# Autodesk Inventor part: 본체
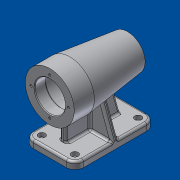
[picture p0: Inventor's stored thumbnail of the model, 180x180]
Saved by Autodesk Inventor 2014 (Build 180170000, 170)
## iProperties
Created: 2018-09
Part Number: 본체
Material: 알루미늄 6061
Document SubType Name: Modeling
Designer: 702-20
Density: 2.71 g/cm^3
Appearance: 알루미늄 - 평지
Mass: 736.704 g
Surface Area: 677.019 cm^2
Volume: 271.846 cm^3
Author: 702-20
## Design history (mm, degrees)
sketch "스케치5"
  geometry: C1 r 34 at (0, 0); 1 further point
  constraints: 1 centre point, 1 coincident
  dimensions: "d16" = 68 diameter of C1
extrude "돌출1" new body sketch "스케치5" distance "d17" = 28; taper "d18" = 0 deg
sketch "스케치6"
  geometry: C1 r 34 at (0, 0) reference
extrude "돌출2" join sketch "스케치6" distance "d19" = 92; taper "d20" = -7 deg
sketch "스케치7"
  geometry: L1 (0, 34)-(28, 34) reference; L2 (0, 34)-(0, -34) reference; L3 (0, -34)-(28, -34) reference; L4 (0, 34)-(117.083, 34); L5 (0, -34)-(117.083, -34); L6 (0, 0)-(112, 0); A1 r 80 centre (32, 0) between (104.415, -34) and (104.415, 34)
  constraints: 6 end point, 4 parallel, 3 point on circle, 2 point on line, 1 centre point
  dimensions: "d21" = 112 distance of L6.end L6.start; "d22" = 80 radius of A1
node "작업 평면2"
sketch "스케치8"
  geometry: L1 (-34, 0)-(-34, 28) reference; L2 (34, 0)-(34, 28) reference; L3 (-34, 0)-(34, 0) reference; L4 (-34, 0)-(-34, 112.065); L5 (34, 0)-(34, 112.065); A1 r 80 centre (-0.332, 24.439) between (45.834, 89.774) and (-45.954, 90.155); 3 further points
  constraints: 4 end point, 3 point on circle, 2 parallel, 1 centre point, 1 coincident, 1 perpendicular, 1 other
  dimensions: "d23" = 80 radius of A1
feature "스윕 곡면2" sketch "스케치8" dims "d24" = 0
feature "분할2"
sketch "스케치9"
  geometry: L1 (0, 0)-(0, 118.713); L2 (0, 106)-(7.5, 106); L3 (10.5, 103)-(10.5, 103); L4 (10.5, 103)-(15.7, 103); L5 (16, 102.7)-(16, 99); L6 (16, 99)-(17.2, 99); L7 (17.5, 98.7)-(17.5, 81); L8 (17.5, 81)-(20.7, 81); L9 (21, 80.7)-(21, 69); L10 (21, 69)-(21, 69); L11 (24, 66)-(24, 18); L12 (21, 15)-(21, 15); L13 (21, 15)-(21, 0); L14 (21, 0)-(0, 0); A1 r 3 centre (7.5, 103) between (10.5, 103) and (7.5, 106); A2 r 3 centre (21, 66) between (24, 66) and (21, 69); A3 r 3 centre (21, 18) between (21, 15) and (24, 18); A4 r 0.3 centre (15.7, 102.7) between (16, 102.7) and (15.7, 103); A5 r 0.3 centre (17.2, 98.7) between (17.5, 98.7) and (17.2, 99); A6 r 0.3 centre (20.7, 80.7) between (21, 80.7) and (20.7, 81); 3 further points
  constraints: 28 end point, 12 point on circle, 12 tangent, 9 parallel, 7 point on line, 6 centre point, 4 equal radius, 4 perpendicular, 1 vertical
  dimensions: "d25" = 15 distance between parallel lines of L14 L12; "d26" = 54 distance between parallel lines of L10 L12; "d27" = 12 distance between parallel lines of L8 L10; "d28" = 18 distance from line of L5.end L8; "d29" = 4 vertical distance of point (16, 103) point (17.5, 99); "d30" = 3 distance between parallel lines of L2 L4; "d31" = 42 diameter of L13 L1; "d32" = 48 diameter of L11 L1; "d33" = 42 diameter of L9 L1; "d34" = 35 diameter of L7 L1; "d35" = 32 diameter of L5 L1; "d36" = 21 diameter of point (10.5, 106) L1; "d37" = 3 radius of A1; "d38" = 0.3 radius of A4
revolve "회전2" sketch "스케치9" stored, may be unused: angle "d39" = 90 deg
node "작업 평면3"
sketch "스케치10"
  geometry: L1 (-23, 112)-(23, 112); L2 (35, 100)-(35, 12); L3 (23, 0)-(-23, 0); L4 (-35, 12)-(-35, 100); A1 r 12 centre (-23, 100) between (-23, 112) and (-35, 100); A2 r 12 centre (23, 100) between (35, 100) and (23, 112); A3 r 12 centre (23, 12) between (23, 0) and (35, 12); A4 r 12 centre (-23, 12) between (-35, 12) and (-23, 0); 5 further points
  constraints: 8 end point, 8 point on circle, 8 tangent, 6 point on line, 4 centre point, 3 equal radius, 2 parallel, 1 coincident, 1 horizontal, 1 midpoint, 1 perpendicular
  dimensions: "d41" = 70 distance of point (35, 0) point (-35, 0); "d42" = 112 distance of point (35, 112) point (35, 0); "d43" = 12 radius of A1
extrude "돌출3" join sketch "스케치10" distance "d44" = 10; taper "d45" = 0 deg
sketch "스케치11"
  geometry: L1 (18, -31.243)-(18, -64); L2 (83.432, -24.56)-(94, -64); L3 (108.27, -24.144)-(28, -34) reference; L4 (28, -34)-(0, -34) reference; L5 (0, -34)-(0, -21) reference; L6 (0, -21)-(15, -21) reference; L7 (18, -24)-(66, -24) reference; L8 (69, -21)-(80.7, -21) reference; L9 (81, -20.7)-(81, -17.5) reference; L10 (81, -17.5)-(98.7, -17.5) reference; L11 (99, -17.2)-(99, -16) reference; L12 (99, -16)-(102.7, -16) reference; L13 (103, -15.7)-(103, -10.5) reference; L14 (106, -7.5)-(106, 7.5) reference; L15 (103, 10.5)-(103, 15.7) reference; L16 (102.7, 16)-(99, 16) reference; L17 (99, 16)-(99, 17.2) reference; L18 (98.7, 17.5)-(81, 17.5) reference; L19 (81, 17.5)-(81, 20.7) reference; L20 (80.7, 21)-(69, 21) reference; L21 (66, 24)-(18, 24) reference; L22 (15, 21)-(0, 21) reference; L23 (0, 21)-(0, 34) reference; L24 (0, 34)-(28, 34) reference; L25 (28, 34)-(108.27, 24.144) reference; L26 (0, -74)-(0, -64) reference; L27 (0, -64)-(112, -64) reference; L28 (112, -64)-(112, -74) reference; L29 (112, -74)-(0, -74) reference; L30 (18, -31.243)-(34.345, -31.243); L31 (34.345, -31.243)-(83.432, -24.56); A1 r 3 centre (18, -21) between (15, -21) and (18, -24) reference; A2 r 3 centre (66, -21) between (66, -24) and (69, -21) reference; A3 r 0.3 centre (80.7, -20.7) between (80.7, -21) and (81, -20.7) reference; A4 r 0.3 centre (98.7, -17.2) between (98.7, -17.5) and (99, -17.2) reference; A5 r 0.3 centre (102.7, -15.7) between (102.7, -16) and (103, -15.7) reference; A6 r 3 centre (103, -7.5) between (103, -10.5) and (106, -7.5) reference; A7 r 3 centre (103, 7.5) between (106, 7.5) and (103, 10.5) reference; A8 r 0.3 centre (102.7, 15.7) between (103, 15.7) and (102.7, 16) reference; A9 r 0.3 centre (98.7, 17.2) between (99, 17.2) and (98.7, 17.5) reference; A10 r 0.3 centre (80.7, 20.7) between (81, 20.7) and (80.7, 21) reference; A11 r 3 centre (66, 21) between (69, 21) and (66, 24) reference; A12 r 3 centre (18, 21) between (18, 24) and (15, 21) reference; 3 further points
  constraints: 8 end point, 6 point on line, 1 parallel, 1 vertical, 1 vertical alignment
  dimensions: "d46" = 18 distance from line of L2.end L28; "d47" = 18 distance between parallel lines of L1 L26; "d48" = 105 deg angle of L2 L27
extrude "돌출4" join sketch "스케치11" stored distance "d49" = 8; taper "d50" = 0 deg
node "작업 평면4"
sketch "스케치12"
  geometry: L1 (35, -64)-(35, -74) reference; L2 (35, -74)-(-35, -74) reference; L3 (-35, -74)-(-35, -64) reference; L4 (-35, -64)-(-4, -64) reference; L5 (-4, -64)-(-4, -30.562) reference; L6 (-4, -30.562)-(0, -30.562) reference; L7 (0, -30.562)-(4, -30.562) reference; L8 (4, -30.562)-(4, -64) reference; L9 (4, -64)-(35, -64) reference; L10 (-35, -64)-(-20.089, -23.032); C1 r 24 at (0, 0) reference; A1 r 30.562 centre (0, 0) between (0, -30.562) and (-20.089, -23.032) reference; 1 further point
  constraints: 2 end point, 1 point on circle
  dimensions: "d53" = 20 deg angle of L10 L3
feature "리브1" sketch "스케치12" dims "d54" = 1, "d55" = 8, "d56" = 0, "d57" = 0, "d58" = 1, "d59" = 1
fillet "모깎기1" dims "d60" = 3
fillet "모깎기2" dims "d61" = 3
fillet "모깎기3" dims "d62" = 3
fillet "모깎기4" dims "d63" = 3
fillet "모깎기5" dims "d64" = 3
fillet "모깎기6" dims "d65" = 3
hole "구멍1" diameter "d68" = 5.5; stored, may be unused: countersink angle "d72" = 90 deg, drill point angle "d74" = 118 deg; dims "d66" = 10, "d67" = 10, "d69" = 6, "d70" = 9.5, "d71" = 5.4, "d73" = 8
node "작업 평면5"
node "작업 평면6"
sketch "스케치13"
  geometry: C1 r 21 at (0, 0) reference; 1 further point
  dimensions: "d75" = 26 distance of C1.centre point (0, 26)
hole "구멍2" sketch "스케치13" at (0, 26) diameter "d76" = 3.242; stored, may be unused: countersink angle "d80" = 90 deg, drill point angle "d82" = 118 deg; dims "d77" = 8, "d78" = 9.5, "d79" = 5.4, "d81" = 11
chamfer "모따기1" distance "d86" = 1; stored, may be unused: second distance "d87" = 2, angle "d88" = 45 deg
sketch "스케치14"
  geometry: L1 (0, 88)-(0, 0) reference; L2 (7, 39.391)-(7, 0) reference; L3 (3, 110.486)-(3, -60.871); L4 (0, 44)-(17.321, 44); 2 further points
  constraints: 4 end point, 1 midpoint, 1 parallel, 1 perpendicular, 1 other
  dimensions: "d89" = 3 distance between parallel lines of L3 L1
feature "엠보싱1" sketch "스케치14" dims "d90" = 0.5, "d91" = 0
node "솔리드2"
mirror "대칭1"
mirror "대칭2"
mirror "대칭3"
pattern_circular "원형 패턴1" dims angle "d84" = 360 deg
node "곡면3"
node "절단 모서리 투영1"
node "절단 모서리 투영2"
other parameters: "d40" = -74, "d51" = 56
